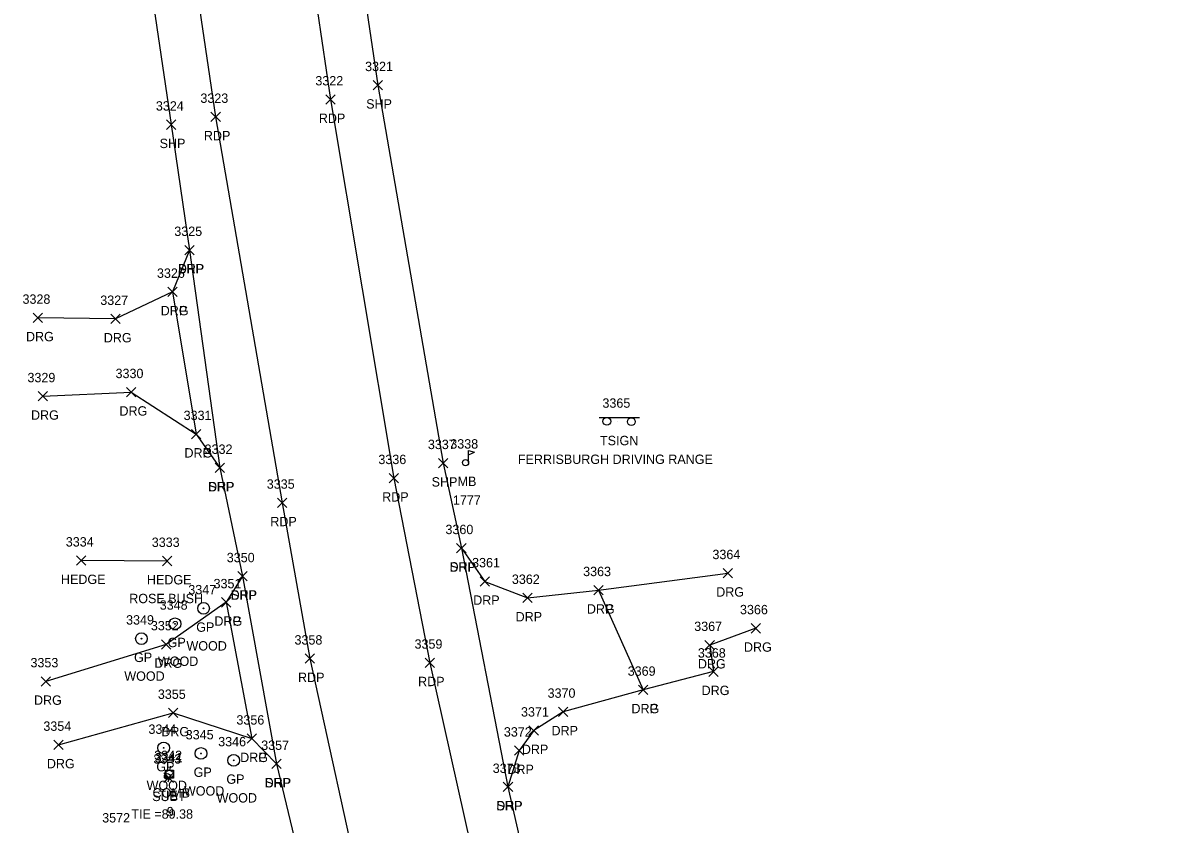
# Model space of a CAD drawing. Extents: x 1443071 to 1445292, y 614024 to 622563.
# Drawn here: x 1444460 to 1444705, y 615443 to 615614.1 of the extents above; entities that cross this region are included whole.
import ezdxf

# ---------------------------------------------------------------- set-up
doc = ezdxf.new("R2010")
doc.units = 0
for name, color, linetype in [('C_A', 7, 'Continuous'), ('C_C', 7, 'Continuous'), ('C_I', 7, 'Continuous'), ('CBP', 7, 'Continuous'), ('L_A', 7, 'Continuous'), ('L_C', 7, 'Continuous'), ('L_I', 7, 'Continuous'), ('L_TIC', 7, 'Continuous'), ('LAHR', 7, 'Continuous'), ('LMB', 7, 'Continuous'), ('M_I', 7, 'Continuous'), ('P_A', 7, 'Continuous'), ('P_I', 7, 'Continuous'), ('P_TIC', 7, 'Continuous'), ('PET', 7, 'Continuous'), ('PSP', 7, 'Continuous'), ('R_A', 7, 'Continuous'), ('R_C', 7, 'Continuous'), ('R_I', 7, 'Continuous'), ('R_TIC', 7, 'Continuous'), ('RDG', 7, 'Continuous'), ('RDP', 7, 'Continuous'), ('RGP', 7, 'Continuous'), ('S_A', 7, 'Continuous'), ('S_C', 7, 'Continuous'), ('S_I', 7, 'Continuous'), ('SSGN', 7, 'Continuous'), ('U_A', 7, 'Continuous'), ('U_C', 7, 'Continuous'), ('U_I', 7, 'Continuous'), ('U_TIC', 7, 'Continuous'), ('UP', 7, 'Continuous')]:
    doc.layers.add(name, color=color, linetype=linetype)

msp = doc.modelspace()

# ---------------------------------------------------------------- linework, layer by layer
at = {"layer": 'CBP'}
for radius in [0.625, 0.0833]:
    msp.add_circle((1444490.78, 615453.18), radius, dxfattribs=at)
at = {"layer": 'L_TIC'}
for points in [[(1444471.37, 615498.28), (1444473.37, 615500.28)], [(1444473.37, 615498.28), (1444471.37, 615500.28)], [(1444489.72, 615498.19), (1444491.72, 615500.19)], [(1444491.72, 615498.19), (1444489.72, 615500.19)]]:
    msp.add_lwpolyline(points, dxfattribs=at)
at = {"layer": 'LAHR'}
msp.add_lwpolyline([(1444490.72, 615499.19), (1444472.37, 615499.28)], dxfattribs=at)
at = {"layer": 'LMB'}
for p, q in [((1444555.08, 615522.79), (1444556.38, 615522.41)), ((1444555.09, 615520.2), (1444555.09, 615522.79)), ((1444555.09, 615521.89), (1444556.37, 615522.4)), ((1444554.43, 615520.19), (1444554.43, 615520.19))]:
    msp.add_line(p, q, dxfattribs=at)
msp.add_circle((1444554.43, 615520.19), 0.656, dxfattribs=at)
at = {"layer": 'P_TIC'}
for points in [[(1444534.69, 615599.77), (1444536.69, 615601.77)], [(1444536.69, 615599.77), (1444534.69, 615601.77)], [(1444524.64, 615596.72), (1444526.64, 615598.72)], [(1444526.64, 615596.72), (1444524.64, 615598.72)], [(1444490.6, 615591.34), (1444492.6, 615593.34)], [(1444492.6, 615591.34), (1444490.6, 615593.34)], [(1444500.1, 615592.99), (1444502.1, 615594.99)], [(1444502.1, 615592.99), (1444500.1, 615594.99)], [(1444494.53, 615564.58), (1444496.53, 615566.58)], [(1444496.53, 615564.58), (1444494.53, 615566.58)], [(1444501, 615518.06), (1444503, 615520.06)], [(1444503, 615518.06), (1444501, 615520.06)], [(1444548.66, 615519.08), (1444550.66, 615521.08)], [(1444550.66, 615519.08), (1444548.66, 615521.08)], [(1444538.15, 615515.88), (1444540.15, 615517.88)], [(1444540.15, 615515.88), (1444538.15, 615517.88)], [(1444514.27, 615510.62), (1444516.27, 615512.62)], [(1444516.27, 615510.62), (1444514.27, 615512.62)], [(1444552.54, 615500.93), (1444554.54, 615502.93)], [(1444554.54, 615500.93), (1444552.54, 615502.93)], [(1444505.81, 615494.93), (1444507.81, 615496.93)], [(1444507.81, 615494.93), (1444505.81, 615496.93)], [(1444520.19, 615477.35), (1444522.19, 615479.35)], [(1444522.19, 615477.35), (1444520.19, 615479.35)], [(1444545.82, 615476.47), (1444547.82, 615478.47)], [(1444547.82, 615476.47), (1444545.82, 615478.47)], [(1444513.08, 615454.86), (1444515.08, 615456.86)], [(1444515.08, 615454.86), (1444513.08, 615456.86)], [(1444562.5, 615449.95), (1444564.5, 615451.95)], [(1444564.5, 615449.95), (1444562.5, 615451.95)]]:
    msp.add_lwpolyline(points, dxfattribs=at)
at = {"layer": 'PET'}
for points in [[(1444515.41, 615666.64), (1444525.64, 615597.72), (1444539.15, 615516.88), (1444546.82, 615477.47), (1444568.77, 615379.04), (1444586.53, 615311.53), (1444610.33, 615232.54), (1444627.09, 615182.96), (1444651.76, 615115.59), (1444677.88, 615049.92), (1444706.69, 614984.38), (1444728.43, 614937.95), (1444768.51, 614858.7), (1444799.15, 614800.99), (1444824.62, 614757.18), (1444865.42, 614691.8), (1444899.77, 614641.45), (1444937.88, 614589.68), (1444998.28, 614514.87), (1445051.44, 614455.88), (1445114.13, 614386.03), (1445184.96, 614305.48), (1445233, 614249.8)], [(1444490.82, 615663.43), (1444501.1, 615593.99), (1444515.27, 615511.62), (1444521.19, 615478.35), (1444544.09, 615373.93), (1444561.44, 615305.44), (1444586.48, 615224.03), (1444602.94, 615175.46), (1444627.39, 615107.06), (1444650.85, 615039.44), (1444675.64, 614974.55), (1444696.75, 614924.47), (1444735.13, 614842.55), (1444765.29, 614784.89)]]:
    msp.add_lwpolyline(points, dxfattribs=at)
at = {"layer": 'PSP'}
for points in [[(1444525.85, 615667.7), (1444535.69, 615600.77), (1444549.66, 615520.08), (1444553.54, 615501.93), (1444563.5, 615450.95), (1444579.41, 615381.07), (1444595.9, 615314.06), (1444619.24, 615236.14), (1444635.55, 615185.75), (1444659.46, 615119.95), (1444685.78, 615053.56), (1444714.86, 614987.25), (1444736.37, 614941.29), (1444776.12, 614863.57), (1444806.96, 614805.44), (1444831.81, 614763.27), (1444872.68, 614696.13), (1444906.86, 614647.72), (1444944.43, 614594.03), (1445004.77, 614520.62), (1445058.5, 614460.6), (1445120.25, 614392.35), (1445191.33, 614311.4), (1445239.24, 614255.89)], [(1444481.34, 615661.86), (1444491.6, 615592.34), (1444495.53, 615565.58), (1444502, 615519.06), (1444506.81, 615495.93), (1444514.08, 615455.86), (1444534.11, 615372.51), (1444552.93, 615304.11), (1444577.65, 615221.25), (1444593.68, 615173.12), (1444618.66, 615104.72), (1444644.27, 615037.2), (1444671.31, 614972.18), (1444691.69, 614923.2), (1444732.4, 614840.77), (1444762.04, 614783.35)]]:
    msp.add_lwpolyline(points, dxfattribs=at)
at = {"layer": 'R_TIC'}
for points in [[(1444494.53, 615564.58), (1444496.53, 615566.58)], [(1444496.53, 615564.58), (1444494.53, 615566.58)], [(1444490.88, 615555.64), (1444492.88, 615557.64)], [(1444492.88, 615555.64), (1444490.88, 615557.64)], [(1444490.88, 615555.64), (1444492.88, 615557.64)], [(1444492.88, 615555.64), (1444490.88, 615557.64)], [(1444462.13, 615550.1), (1444464.13, 615552.1)], [(1444464.13, 615550.1), (1444462.13, 615552.1)], [(1444478.73, 615549.86), (1444480.73, 615551.86)], [(1444480.73, 615549.86), (1444478.73, 615551.86)], [(1444463.19, 615533.35), (1444465.19, 615535.35)], [(1444465.19, 615533.35), (1444463.19, 615535.35)], [(1444482.07, 615534.23), (1444484.07, 615536.23)], [(1444484.07, 615534.23), (1444482.07, 615536.23)], [(1444495.95, 615525.28), (1444497.95, 615527.28)], [(1444497.95, 615525.28), (1444495.95, 615527.28)], [(1444495.95, 615525.28), (1444497.95, 615527.28)], [(1444497.95, 615525.28), (1444495.95, 615527.28)], [(1444501, 615518.06), (1444503, 615520.06)], [(1444503, 615518.06), (1444501, 615520.06)], [(1444552.54, 615500.93), (1444554.54, 615502.93)], [(1444554.54, 615500.93), (1444552.54, 615502.93)], [(1444609.45, 615495.59), (1444611.45, 615497.59)], [(1444611.45, 615495.59), (1444609.45, 615497.59)], [(1444505.81, 615494.93), (1444507.81, 615496.93)], [(1444507.81, 615494.93), (1444505.81, 615496.93)], [(1444557.58, 615493.84), (1444559.58, 615495.84)], [(1444559.58, 615493.84), (1444557.58, 615495.84)], [(1444581.85, 615491.96), (1444583.85, 615493.96)], [(1444583.85, 615491.96), (1444581.85, 615493.96)], [(1444581.85, 615491.96), (1444583.85, 615493.96)], [(1444583.85, 615491.96), (1444581.85, 615493.96)], [(1444502.34, 615489.37), (1444504.34, 615491.37)], [(1444504.34, 615489.37), (1444502.34, 615491.37)], [(1444502.34, 615489.37), (1444504.34, 615491.37)], [(1444504.34, 615489.37), (1444502.34, 615491.37)], [(1444566.64, 615490.3), (1444568.64, 615492.3)], [(1444568.64, 615490.3), (1444566.64, 615492.3)], [(1444615.39, 615483.82), (1444617.39, 615485.82)], [(1444617.39, 615483.82), (1444615.39, 615485.82)], [(1444489.53, 615480.39), (1444491.53, 615482.39)], [(1444491.53, 615480.39), (1444489.53, 615482.39)], [(1444605.55, 615480.25), (1444607.55, 615482.25)], [(1444607.55, 615480.25), (1444605.55, 615482.25)], [(1444606.34, 615474.57), (1444608.34, 615476.57)], [(1444608.34, 615474.57), (1444606.34, 615476.57)], [(1444463.83, 615472.49), (1444465.83, 615474.49)], [(1444465.83, 615472.49), (1444463.83, 615474.49)], [(1444591.36, 615470.69), (1444593.36, 615472.69)], [(1444593.36, 615470.69), (1444591.36, 615472.69)], [(1444591.36, 615470.69), (1444593.36, 615472.69)], [(1444593.36, 615470.69), (1444591.36, 615472.69)], [(1444574.3, 615465.99), (1444576.3, 615467.99)], [(1444576.3, 615465.99), (1444574.3, 615467.99)], [(1444491.02, 615465.76), (1444493.02, 615467.76)], [(1444493.02, 615465.76), (1444491.02, 615467.76)], [(1444567.98, 615461.98), (1444569.98, 615463.98)], [(1444569.98, 615461.98), (1444567.98, 615463.98)], [(1444466.58, 615458.94), (1444468.58, 615460.94)], [(1444468.58, 615458.94), (1444466.58, 615460.94)], [(1444507.84, 615460.27), (1444509.84, 615462.27)], [(1444509.84, 615460.27), (1444507.84, 615462.27)], [(1444507.84, 615460.27), (1444509.84, 615462.27)], [(1444509.84, 615460.27), (1444507.84, 615462.27)], [(1444564.88, 615457.71), (1444566.88, 615459.71)], [(1444566.88, 615457.71), (1444564.88, 615459.71)], [(1444513.08, 615454.86), (1444515.08, 615456.86)], [(1444515.08, 615454.86), (1444513.08, 615456.86)], [(1444562.5, 615449.95), (1444564.5, 615451.95)], [(1444564.5, 615449.95), (1444562.5, 615451.95)]]:
    msp.add_lwpolyline(points, dxfattribs=at)
at = {"layer": 'RDG'}
for points in [[(1444491.88, 615556.64), (1444479.73, 615550.86), (1444463.13, 615551.1)], [(1444464.19, 615534.35), (1444483.07, 615535.23), (1444496.95, 615526.28)], [(1444582.85, 615492.96), (1444610.45, 615496.59)], [(1444503.34, 615490.37), (1444490.53, 615481.39), (1444464.83, 615473.49)], [(1444616.39, 615484.82), (1444606.55, 615481.25), (1444607.34, 615475.57), (1444592.36, 615471.69)], [(1444467.58, 615459.94), (1444492.02, 615466.76), (1444508.84, 615461.27)]]:
    msp.add_lwpolyline(points, dxfattribs=at)
at = {"layer": 'RDP'}
for points in [[(1444495.53, 615565.58), (1444491.88, 615556.64), (1444496.95, 615526.28), (1444502, 615519.06)], [(1444553.54, 615501.93), (1444558.58, 615494.84), (1444567.64, 615491.3), (1444582.85, 615492.96), (1444592.36, 615471.69), (1444575.3, 615466.99), (1444568.98, 615462.98), (1444565.88, 615458.71), (1444563.5, 615450.95)], [(1444506.81, 615495.93), (1444503.34, 615490.37), (1444508.84, 615461.27), (1444514.08, 615455.86)]]:
    msp.add_lwpolyline(points, dxfattribs=at)
at = {"layer": 'RGP'}
for p, q in [((1444498.51, 615489.08), (1444498.51, 615489.08)), ((1444492.42, 615485.8), (1444492.42, 615485.8)), ((1444485.25, 615482.62), (1444485.25, 615482.62)), ((1444490.01, 615459.29), (1444490.01, 615459.29)), ((1444497.97, 615458.11), (1444497.97, 615458.11)), ((1444504.95, 615456.63), (1444504.95, 615456.63))]:
    msp.add_line(p, q, dxfattribs=at)
for centre, radius in [((1444498.51, 615489.08), 1.25), ((1444498.51, 615489.08), 0.0833), ((1444492.42, 615485.8), 1.25), ((1444492.42, 615485.8), 0.0833), ((1444485.25, 615482.62), 1.25), ((1444485.25, 615482.62), 0.0833), ((1444490.01, 615459.29), 1.25), ((1444490.01, 615459.29), 0.0833), ((1444497.97, 615458.11), 1.25), ((1444497.97, 615458.11), 0.0833), ((1444504.95, 615456.63), 1.25), ((1444504.95, 615456.63), 0.0833)]:
    msp.add_circle(centre, radius, dxfattribs=at)
at = {"layer": 'SSGN'}
for p, q in [((1444582.95, 615529.83), (1444591.54, 615529.83)), ((1444586.97, 615528.93), (1444586.97, 615528.93))]:
    msp.add_line(p, q, dxfattribs=at)
for centre in [(1444584.61, 615529), (1444589.82, 615528.93)]:
    msp.add_circle(centre, 0.833, dxfattribs=at)
at = {"layer": 'U_TIC'}
for points in [[(1444490.07, 615451.94), (1444492.07, 615453.94)], [(1444492.07, 615451.94), (1444490.07, 615453.94)]]:
    msp.add_lwpolyline(points, dxfattribs=at)
at = {"layer": 'UP'}
for p, q in [((1444490.4, 615452.86), (1444490.4, 615454.52)), ((1444490.4, 615454.52), (1444492.07, 615454.52)), ((1444491.49, 615455.36), (1444491.24, 615454.52)), ((1444491.24, 615453.69), (1444491.24, 615453.69)), ((1444492.07, 615454.52), (1444492.07, 615452.86)), ((1444492.07, 615452.86), (1444490.4, 615452.86)), ((1444490.99, 615452.02), (1444491.24, 615452.86))]:
    msp.add_line(p, q, dxfattribs=at)
msp.add_circle((1444491.24, 615453.69), 0.833, dxfattribs=at)

# ---------------------------------------------------------------- texts
at = {"layer": 'C_A'}
msp.add_text('TIE', height=2, dxfattribs=at).set_placement((1444488.86, 615448.18))
at = {"layer": 'C_C'}
msp.add_text('TIE =89.38', height=2, dxfattribs=at).set_placement((1444483.11, 615444.18))
at = {"layer": 'C_I'}
msp.add_text('3341', height=2, dxfattribs=at).set_placement((1444488.09, 615456.18))
at = {"layer": 'L_A'}
for s, p in [('MB', (1444552.74, 615515.19)), ('HEDGE', (1444468.08, 615494.28)), ('HEDGE', (1444486.43, 615494.19))]:
    msp.add_text(s, height=2, dxfattribs=at).set_placement(p)
at = {"layer": 'L_C'}
for s, p in [('1777', (1444551.74, 615511.19)), ('ROSE BUSH', (1444482.65, 615490.19))]:
    msp.add_text(s, height=2, dxfattribs=at).set_placement(p)
at = {"layer": 'L_I'}
for s, p in [('3338', (1444551.18, 615523.19)), ('3334', (1444469.11, 615502.28)), ('3333', (1444487.46, 615502.19))]:
    msp.add_text(s, height=2, dxfattribs=at).set_placement(p)
at = {"layer": 'M_I'}
msp.add_text('3572', height=2, dxfattribs=at).set_placement((1444476.88, 615443.37))
at = {"layer": 'P_A'}
for s, p in [('SHP', (1444533.23, 615595.77)), ('RDP', (1444523.12, 615592.72)), ('RDP', (1444498.59, 615588.99)), ('SHP', (1444489.14, 615587.34)), ('SHP', (1444493.07, 615560.58)), ('SHP', (1444547.2, 615515.08)), ('SHP', (1444499.53, 615514.06)), ('RDP', (1444536.64, 615511.88)), ('RDP', (1444512.76, 615506.62)), ('SHP', (1444551.08, 615496.93)), ('SHP', (1444504.35, 615490.93)), ('RDP', (1444518.68, 615473.35)), ('RDP', (1444544.31, 615472.47)), ('SHP', (1444511.62, 615450.86)), ('SHP', (1444561.03, 615445.95))]:
    msp.add_text(s, height=2, dxfattribs=at).set_placement(p)
at = {"layer": 'P_I'}
for s, p in [('3321', (1444533, 615603.77)), ('3322', (1444522.38, 615600.72)), ('3323', (1444497.84, 615596.99)), ('3324', (1444488.34, 615595.34)), ('3325', (1444492.27, 615568.58)), ('3337', (1444546.4, 615523.08)), ('3332', (1444498.74, 615522.06)), ('3336', (1444535.83, 615519.88)), ('3335', (1444512.01, 615514.62)), ('3360', (1444550.15, 615504.93)), ('3350', (1444503.47, 615498.93)), ('3358', (1444517.93, 615481.35)), ('3359', (1444543.55, 615480.47)), ('3357', (1444510.82, 615458.86)), ('3373', (1444560.24, 615453.95))]:
    msp.add_text(s, height=2, dxfattribs=at).set_placement(p)
at = {"layer": 'R_A'}
for s, p in [('DRP', (1444493.02, 615560.58)), ('DRG', (1444489.37, 615551.64)), ('DRP', (1444489.37, 615551.64)), ('DRG', (1444460.61, 615546.1)), ('DRG', (1444477.22, 615545.86)), ('DRG', (1444480.56, 615530.23)), ('DRG', (1444461.68, 615529.35)), ('DRG', (1444494.44, 615521.28)), ('DRP', (1444494.44, 615521.28)), ('DRP', (1444499.48, 615514.06)), ('DRP', (1444551.03, 615496.93)), ('DRP', (1444504.3, 615490.93)), ('DRG', (1444607.94, 615491.59)), ('DRP', (1444556.07, 615489.84)), ('DRP', (1444565.13, 615486.3)), ('DRG', (1444580.34, 615487.96)), ('DRP', (1444580.34, 615487.96)), ('GP', (1444496.95, 615484.08)), ('DRG', (1444500.83, 615485.37)), ('DRP', (1444500.83, 615485.37)), ('GP', (1444490.85, 615480.8)), ('DRG', (1444613.87, 615479.82)), ('GP', (1444483.68, 615477.62)), ('DRG', (1444488.02, 615476.39)), ('DRG', (1444604.04, 615476.25)), ('DRG', (1444462.32, 615468.49)), ('DRG', (1444604.83, 615470.57)), ('DRG', (1444589.85, 615466.69)), ('DRP', (1444589.85, 615466.69)), ('DRG', (1444489.5, 615461.76)), ('DRP', (1444572.79, 615461.99)), ('DRG', (1444506.33, 615456.27)), ('DRP', (1444506.33, 615456.27)), ('DRP', (1444566.46, 615457.98)), ('DRG', (1444465.07, 615454.94)), ('GP', (1444488.44, 615454.29)), ('GP', (1444496.4, 615453.11)), ('GP', (1444503.39, 615451.63)), ('DRP', (1444563.37, 615453.71)), ('DRP', (1444511.57, 615450.86)), ('DRP', (1444560.98, 615445.95))]:
    msp.add_text(s, height=2, dxfattribs=at).set_placement(p)
at = {"layer": 'R_C'}
for p in [(1444494.87, 615480.08), (1444488.78, 615476.8), (1444481.6, 615473.62), (1444486.36, 615450.29), (1444494.33, 615449.11), (1444501.31, 615447.63)]:
    msp.add_text('WOOD', height=2, dxfattribs=at).set_placement(p)
at = {"layer": 'R_I'}
for s, p in [('3325', (1444492.27, 615568.58)), ('3326', (1444488.57, 615559.64)), ('3326', (1444488.57, 615559.64)), ('3328', (1444459.87, 615554.1)), ('3327', (1444476.47, 615553.86)), ('3329', (1444460.93, 615537.35)), ('3330', (1444479.73, 615538.23)), ('3331', (1444494.26, 615529.28)), ('3331', (1444494.26, 615529.28)), ('3332', (1444498.74, 615522.06)), ('3360', (1444550.15, 615504.93)), ('3350', (1444503.47, 615498.93)), ('3361', (1444555.84, 615497.84)), ('3364', (1444607.14, 615499.59)), ('3363', (1444579.54, 615495.96)), ('3363', (1444579.54, 615495.96)), ('3351', (1444500.65, 615493.37)), ('3351', (1444500.65, 615493.37)), ('3362', (1444564.33, 615494.3)), ('3347', (1444495.26, 615492.08)), ('3348', (1444489.16, 615488.8)), ('3349', (1444481.98, 615485.62)), ('3366', (1444613.02, 615487.82)), ('3352', (1444487.27, 615484.39)), ('3367', (1444603.25, 615484.25)), ('3368', (1444604.03, 615478.57)), ('3353', (1444461.57, 615476.49)), ('3369', (1444589.05, 615474.69)), ('3369', (1444589.05, 615474.69)), ('3355', (1444488.76, 615469.76)), ('3370', (1444571.95, 615469.99)), ('3371', (1444566.28, 615465.98)), ('3356', (1444505.53, 615464.27)), ('3356', (1444505.53, 615464.27)), ('3354', (1444464.32, 615462.94)), ('3344', (1444486.75, 615462.29)), ('3345', (1444494.71, 615461.11)), ('3372', (1444562.62, 615461.71)), ('3346', (1444501.64, 615459.63)), ('3357', (1444510.82, 615458.86)), ('3373', (1444560.24, 615453.95))]:
    msp.add_text(s, height=2, dxfattribs=at).set_placement(p)
at = {"layer": 'S_A'}
msp.add_text('TSIGN', height=2, dxfattribs=at).set_placement((1444583.14, 615523.91))
at = {"layer": 'S_C'}
msp.add_text('FERRISBURGH DRIVING RANGE', height=2, dxfattribs=at).set_placement((1444565.62, 615519.91))
at = {"layer": 'S_I'}
msp.add_text('3365', height=2, dxfattribs=at).set_placement((1444583.66, 615531.91))
at = {"layer": 'U_A'}
for s, p in [('SUBT', (1444487.56, 615447.94)), ('COMB', (1444487.62, 615448.69))]:
    msp.add_text(s, height=2, dxfattribs=at).set_placement(p)
at = {"layer": 'U_C'}
msp.add_text('9', height=2, dxfattribs=at).set_placement((1444490.66, 615444.69))
at = {"layer": 'U_I'}
for s, p in [('3342', (1444487.98, 615456.69)), ('3343', (1444487.81, 615455.94))]:
    msp.add_text(s, height=2, dxfattribs=at).set_placement(p)

doc.saveas('drawing.dxf')
